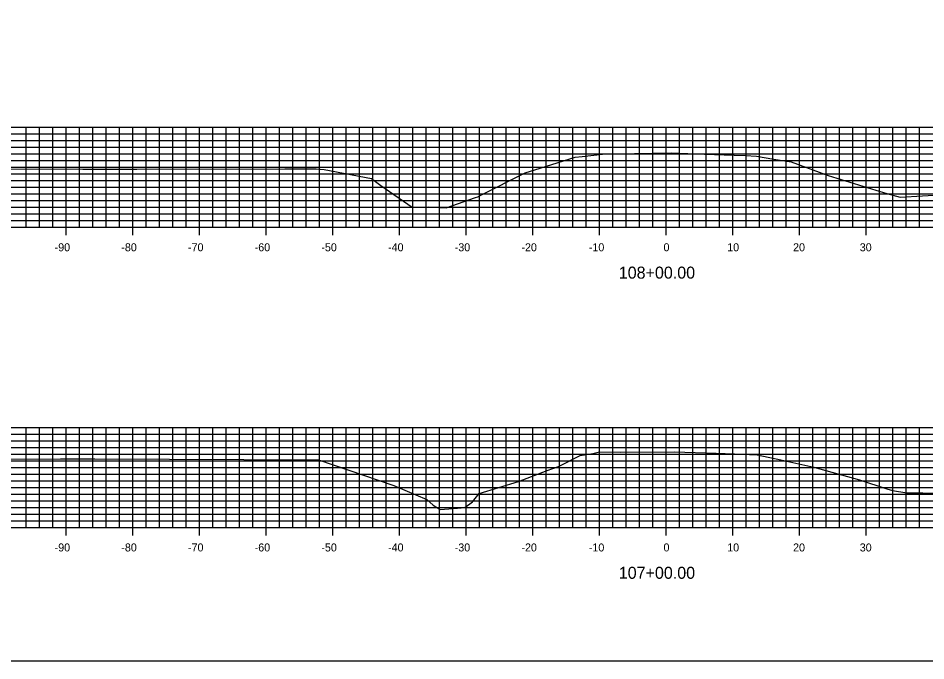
# Model space of a CAD drawing. Extents: x 1661012 to 1662122, y 670053 to 671852.
# Drawn here: x 1661094.8 to 1661230.9, y 671274.1 to 671370.5 of the extents above; entities that cross this region are included whole.
import ezdxf

# ---------------------------------------------------------------- set-up
doc = ezdxf.new("R2010")
doc.units = 0
for name, color, linetype in [('R_Concrete', 7, 'Continuous'), ('R_Concrete Hidden', 7, 'Continuous'), ('R_Erosion', 7, 'Continuous'), ('R_Exist Surface', 7, 'Continuous'), ('R_Proposed Road', 7, 'Continuous')]:
    doc.layers.add(name, color=color, linetype=linetype)

msp = doc.modelspace()

# ---------------------------------------------------------------- linework, layer by layer
at = {"layer": 'R_Concrete'}
for p, q in [((1661041.99, 671354.12), (1661341.99, 671354.12)), ((1661041.99, 671353.12), (1661341.99, 671353.12)), ((1661095.99, 671339.12), (1661095.99, 671354.12)), ((1661097.99, 671339.12), (1661097.99, 671354.12)), ((1661099.99, 671339.12), (1661099.99, 671354.12)), ((1661101.99, 671339.12), (1661101.99, 671354.12)), ((1661103.99, 671339.12), (1661103.99, 671354.12)), ((1661105.99, 671339.12), (1661105.99, 671354.12)), ((1661107.99, 671339.12), (1661107.99, 671354.12)), ((1661109.99, 671339.12), (1661109.99, 671354.12)), ((1661111.99, 671339.12), (1661111.99, 671354.12)), ((1661113.99, 671339.12), (1661113.99, 671354.12)), ((1661115.99, 671339.12), (1661115.99, 671354.12)), ((1661117.99, 671339.12), (1661117.99, 671354.12)), ((1661119.99, 671339.12), (1661119.99, 671354.12)), ((1661121.99, 671339.12), (1661121.99, 671354.12)), ((1661123.99, 671339.12), (1661123.99, 671354.12)), ((1661125.99, 671339.12), (1661125.99, 671354.12)), ((1661127.99, 671339.12), (1661127.99, 671354.12)), ((1661129.99, 671339.12), (1661129.99, 671354.12)), ((1661131.99, 671339.12), (1661131.99, 671354.12)), ((1661133.99, 671339.12), (1661133.99, 671354.12)), ((1661135.99, 671339.12), (1661135.99, 671354.12)), ((1661137.99, 671339.12), (1661137.99, 671354.12)), ((1661139.99, 671339.12), (1661139.99, 671354.12)), ((1661141.99, 671339.12), (1661141.99, 671354.12)), ((1661143.99, 671339.12), (1661143.99, 671354.12)), ((1661145.99, 671339.12), (1661145.99, 671354.12)), ((1661147.99, 671339.12), (1661147.99, 671354.12)), ((1661149.99, 671339.12), (1661149.99, 671354.12)), ((1661151.99, 671339.12), (1661151.99, 671354.12)), ((1661153.99, 671339.12), (1661153.99, 671354.12)), ((1661155.99, 671339.12), (1661155.99, 671354.12)), ((1661157.99, 671339.12), (1661157.99, 671354.12)), ((1661159.99, 671339.12), (1661159.99, 671354.12)), ((1661161.99, 671339.12), (1661161.99, 671354.12)), ((1661163.99, 671339.12), (1661163.99, 671354.12)), ((1661165.99, 671339.12), (1661165.99, 671354.12)), ((1661167.99, 671339.12), (1661167.99, 671354.12)), ((1661169.99, 671339.12), (1661169.99, 671354.12)), ((1661171.99, 671339.12), (1661171.99, 671354.12)), ((1661173.99, 671339.12), (1661173.99, 671354.12)), ((1661175.99, 671339.12), (1661175.99, 671354.12)), ((1661177.99, 671339.12), (1661177.99, 671354.12)), ((1661179.99, 671339.12), (1661179.99, 671354.12)), ((1661181.99, 671339.12), (1661181.99, 671354.12)), ((1661183.99, 671339.12), (1661183.99, 671354.12)), ((1661185.99, 671339.12), (1661185.99, 671354.12)), ((1661187.99, 671339.12), (1661187.99, 671354.12)), ((1661189.99, 671339.12), (1661189.99, 671354.12)), ((1661191.99, 671339.12), (1661191.99, 671354.12)), ((1661193.99, 671339.12), (1661193.99, 671354.12)), ((1661195.99, 671339.12), (1661195.99, 671354.12)), ((1661197.99, 671339.12), (1661197.99, 671354.12)), ((1661199.99, 671339.12), (1661199.99, 671354.12)), ((1661201.99, 671339.12), (1661201.99, 671354.12)), ((1661203.99, 671339.12), (1661203.99, 671354.12)), ((1661205.99, 671339.12), (1661205.99, 671354.12)), ((1661207.99, 671339.12), (1661207.99, 671354.12)), ((1661209.99, 671339.12), (1661209.99, 671354.12)), ((1661211.99, 671339.12), (1661211.99, 671354.12)), ((1661213.99, 671339.12), (1661213.99, 671354.12)), ((1661215.99, 671339.12), (1661215.99, 671354.12)), ((1661217.99, 671339.12), (1661217.99, 671354.12)), ((1661219.99, 671339.12), (1661219.99, 671354.12)), ((1661221.99, 671339.12), (1661221.99, 671354.12)), ((1661223.99, 671339.12), (1661223.99, 671354.12)), ((1661225.99, 671339.12), (1661225.99, 671354.12)), ((1661227.99, 671339.12), (1661227.99, 671354.12)), ((1661229.99, 671339.12), (1661229.99, 671354.12)), ((1661041.99, 671352.12), (1661341.99, 671352.12)), ((1661041.99, 671351.12), (1661341.99, 671351.12)), ((1661041.99, 671350.12), (1661341.99, 671350.12)), ((1661041.99, 671349.12), (1661341.99, 671349.12)), ((1661041.99, 671348.12), (1661341.99, 671348.12)), ((1661041.99, 671347.12), (1661341.99, 671347.12)), ((1661041.99, 671346.12), (1661341.99, 671346.12)), ((1661041.99, 671345.12), (1661341.99, 671345.12)), ((1661041.99, 671344.12), (1661341.99, 671344.12)), ((1661041.99, 671343.12), (1661341.99, 671343.12)), ((1661041.99, 671342.12), (1661341.99, 671342.12)), ((1661041.99, 671341.12), (1661341.99, 671341.12)), ((1661041.99, 671340.12), (1661341.99, 671340.12)), ((1661095.99, 671339.12), (1661095.99, 671339.72)), ((1661097.99, 671339.12), (1661097.99, 671339.72)), ((1661099.99, 671339.12), (1661099.99, 671339.72)), ((1661101.99, 671337.92), (1661101.99, 671340.32)), ((1661103.99, 671339.12), (1661103.99, 671339.72)), ((1661105.99, 671339.12), (1661105.99, 671339.72)), ((1661107.99, 671339.12), (1661107.99, 671339.72)), ((1661109.99, 671339.12), (1661109.99, 671339.72)), ((1661111.99, 671337.92), (1661111.99, 671340.32)), ((1661113.99, 671339.12), (1661113.99, 671339.72)), ((1661115.99, 671339.12), (1661115.99, 671339.72)), ((1661117.99, 671339.12), (1661117.99, 671339.72)), ((1661119.99, 671339.12), (1661119.99, 671339.72)), ((1661121.99, 671337.92), (1661121.99, 671340.32)), ((1661123.99, 671339.12), (1661123.99, 671339.72)), ((1661125.99, 671339.12), (1661125.99, 671339.72)), ((1661127.99, 671339.12), (1661127.99, 671339.72)), ((1661129.99, 671339.12), (1661129.99, 671339.72)), ((1661131.99, 671337.92), (1661131.99, 671340.32)), ((1661133.99, 671339.12), (1661133.99, 671339.72)), ((1661135.99, 671339.12), (1661135.99, 671339.72)), ((1661137.99, 671339.12), (1661137.99, 671339.72)), ((1661139.99, 671339.12), (1661139.99, 671339.72)), ((1661141.99, 671337.92), (1661141.99, 671340.32)), ((1661143.99, 671339.12), (1661143.99, 671339.72)), ((1661145.99, 671339.12), (1661145.99, 671339.72)), ((1661147.99, 671339.12), (1661147.99, 671339.72)), ((1661149.99, 671339.12), (1661149.99, 671339.72)), ((1661151.99, 671337.92), (1661151.99, 671340.32)), ((1661153.99, 671339.12), (1661153.99, 671339.72)), ((1661155.99, 671339.12), (1661155.99, 671339.72)), ((1661157.99, 671339.12), (1661157.99, 671339.72)), ((1661159.99, 671339.12), (1661159.99, 671339.72)), ((1661161.99, 671337.92), (1661161.99, 671340.32)), ((1661163.99, 671339.12), (1661163.99, 671339.72)), ((1661165.99, 671339.12), (1661165.99, 671339.72)), ((1661167.99, 671339.12), (1661167.99, 671339.72)), ((1661169.99, 671339.12), (1661169.99, 671339.72)), ((1661171.99, 671337.92), (1661171.99, 671340.32)), ((1661173.99, 671339.12), (1661173.99, 671339.72)), ((1661175.99, 671339.12), (1661175.99, 671339.72)), ((1661177.99, 671339.12), (1661177.99, 671339.72)), ((1661179.99, 671339.12), (1661179.99, 671339.72)), ((1661181.99, 671337.92), (1661181.99, 671340.32)), ((1661183.99, 671339.12), (1661183.99, 671339.72)), ((1661185.99, 671339.12), (1661185.99, 671339.72)), ((1661187.99, 671339.12), (1661187.99, 671339.72)), ((1661189.99, 671339.12), (1661189.99, 671339.72)), ((1661191.99, 671337.92), (1661191.99, 671340.32)), ((1661193.99, 671339.12), (1661193.99, 671339.72)), ((1661195.99, 671339.12), (1661195.99, 671339.72)), ((1661197.99, 671339.12), (1661197.99, 671339.72)), ((1661199.99, 671339.12), (1661199.99, 671339.72)), ((1661201.99, 671337.92), (1661201.99, 671340.32)), ((1661203.99, 671339.12), (1661203.99, 671339.72)), ((1661205.99, 671339.12), (1661205.99, 671339.72)), ((1661207.99, 671339.12), (1661207.99, 671339.72)), ((1661209.99, 671339.12), (1661209.99, 671339.72)), ((1661211.99, 671337.92), (1661211.99, 671340.32)), ((1661213.99, 671339.12), (1661213.99, 671339.72)), ((1661215.99, 671339.12), (1661215.99, 671339.72)), ((1661217.99, 671339.12), (1661217.99, 671339.72)), ((1661219.99, 671339.12), (1661219.99, 671339.72)), ((1661221.99, 671337.92), (1661221.99, 671340.32)), ((1661223.99, 671339.12), (1661223.99, 671339.72)), ((1661225.99, 671339.12), (1661225.99, 671339.72)), ((1661227.99, 671339.12), (1661227.99, 671339.72)), ((1661229.99, 671339.12), (1661229.99, 671339.72)), ((1661041.99, 671339.12), (1661341.99, 671339.12)), ((1661041.99, 671309.12), (1661341.99, 671309.12)), ((1661041.99, 671308.12), (1661341.99, 671308.12)), ((1661095.99, 671294.12), (1661095.99, 671309.12)), ((1661097.99, 671294.12), (1661097.99, 671309.12)), ((1661099.99, 671294.12), (1661099.99, 671309.12)), ((1661101.99, 671294.12), (1661101.99, 671309.12)), ((1661103.99, 671294.12), (1661103.99, 671309.12)), ((1661105.99, 671294.12), (1661105.99, 671309.12)), ((1661107.99, 671294.12), (1661107.99, 671309.12)), ((1661109.99, 671294.12), (1661109.99, 671309.12)), ((1661111.99, 671294.12), (1661111.99, 671309.12)), ((1661113.99, 671294.12), (1661113.99, 671309.12)), ((1661115.99, 671294.12), (1661115.99, 671309.12)), ((1661117.99, 671294.12), (1661117.99, 671309.12)), ((1661119.99, 671294.12), (1661119.99, 671309.12)), ((1661121.99, 671294.12), (1661121.99, 671309.12)), ((1661123.99, 671294.12), (1661123.99, 671309.12)), ((1661125.99, 671294.12), (1661125.99, 671309.12)), ((1661127.99, 671294.12), (1661127.99, 671309.12)), ((1661129.99, 671294.12), (1661129.99, 671309.12)), ((1661131.99, 671294.12), (1661131.99, 671309.12)), ((1661133.99, 671294.12), (1661133.99, 671309.12)), ((1661135.99, 671294.12), (1661135.99, 671309.12)), ((1661137.99, 671294.12), (1661137.99, 671309.12)), ((1661139.99, 671294.12), (1661139.99, 671309.12)), ((1661141.99, 671294.12), (1661141.99, 671309.12)), ((1661143.99, 671294.12), (1661143.99, 671309.12)), ((1661145.99, 671294.12), (1661145.99, 671309.12)), ((1661147.99, 671294.12), (1661147.99, 671309.12)), ((1661149.99, 671294.12), (1661149.99, 671309.12)), ((1661151.99, 671294.12), (1661151.99, 671309.12)), ((1661153.99, 671294.12), (1661153.99, 671309.12)), ((1661155.99, 671294.12), (1661155.99, 671309.12)), ((1661157.99, 671294.12), (1661157.99, 671309.12)), ((1661159.99, 671294.12), (1661159.99, 671309.12)), ((1661161.99, 671294.12), (1661161.99, 671309.12)), ((1661163.99, 671294.12), (1661163.99, 671309.12)), ((1661165.99, 671294.12), (1661165.99, 671309.12)), ((1661167.99, 671294.12), (1661167.99, 671309.12)), ((1661169.99, 671294.12), (1661169.99, 671309.12)), ((1661171.99, 671294.12), (1661171.99, 671309.12)), ((1661173.99, 671294.12), (1661173.99, 671309.12)), ((1661175.99, 671294.12), (1661175.99, 671309.12)), ((1661177.99, 671294.12), (1661177.99, 671309.12)), ((1661179.99, 671294.12), (1661179.99, 671309.12)), ((1661181.99, 671294.12), (1661181.99, 671309.12)), ((1661183.99, 671294.12), (1661183.99, 671309.12)), ((1661185.99, 671294.12), (1661185.99, 671309.12)), ((1661187.99, 671294.12), (1661187.99, 671309.12)), ((1661189.99, 671294.12), (1661189.99, 671309.12)), ((1661191.99, 671294.12), (1661191.99, 671309.12)), ((1661193.99, 671294.12), (1661193.99, 671309.12)), ((1661195.99, 671294.12), (1661195.99, 671309.12)), ((1661197.99, 671294.12), (1661197.99, 671309.12)), ((1661199.99, 671294.12), (1661199.99, 671309.12)), ((1661201.99, 671294.12), (1661201.99, 671309.12)), ((1661203.99, 671294.12), (1661203.99, 671309.12)), ((1661205.99, 671294.12), (1661205.99, 671309.12)), ((1661207.99, 671294.12), (1661207.99, 671309.12)), ((1661209.99, 671294.12), (1661209.99, 671309.12)), ((1661211.99, 671294.12), (1661211.99, 671309.12)), ((1661213.99, 671294.12), (1661213.99, 671309.12)), ((1661215.99, 671294.12), (1661215.99, 671309.12)), ((1661217.99, 671294.12), (1661217.99, 671309.12)), ((1661219.99, 671294.12), (1661219.99, 671309.12)), ((1661221.99, 671294.12), (1661221.99, 671309.12)), ((1661223.99, 671294.12), (1661223.99, 671309.12)), ((1661225.99, 671294.12), (1661225.99, 671309.12)), ((1661227.99, 671294.12), (1661227.99, 671309.12)), ((1661229.99, 671294.12), (1661229.99, 671309.12)), ((1661041.99, 671307.12), (1661341.99, 671307.12)), ((1661041.99, 671306.12), (1661341.99, 671306.12)), ((1661041.99, 671305.12), (1661341.99, 671305.12)), ((1661041.99, 671304.12), (1661341.99, 671304.12)), ((1661041.99, 671303.12), (1661341.99, 671303.12)), ((1661041.99, 671302.12), (1661341.99, 671302.12)), ((1661041.99, 671301.12), (1661341.99, 671301.12)), ((1661041.99, 671300.12), (1661341.99, 671300.12)), ((1661041.99, 671299.12), (1661341.99, 671299.12)), ((1661041.99, 671298.12), (1661341.99, 671298.12)), ((1661041.99, 671297.12), (1661341.99, 671297.12)), ((1661041.99, 671296.12), (1661341.99, 671296.12)), ((1661041.99, 671295.12), (1661341.99, 671295.12)), ((1661095.99, 671294.12), (1661095.99, 671294.72)), ((1661097.99, 671294.12), (1661097.99, 671294.72)), ((1661099.99, 671294.12), (1661099.99, 671294.72)), ((1661101.99, 671292.92), (1661101.99, 671295.32)), ((1661103.99, 671294.12), (1661103.99, 671294.72)), ((1661105.99, 671294.12), (1661105.99, 671294.72)), ((1661107.99, 671294.12), (1661107.99, 671294.72)), ((1661109.99, 671294.12), (1661109.99, 671294.72)), ((1661111.99, 671292.92), (1661111.99, 671295.32)), ((1661113.99, 671294.12), (1661113.99, 671294.72)), ((1661115.99, 671294.12), (1661115.99, 671294.72)), ((1661117.99, 671294.12), (1661117.99, 671294.72)), ((1661119.99, 671294.12), (1661119.99, 671294.72)), ((1661121.99, 671292.92), (1661121.99, 671295.32)), ((1661123.99, 671294.12), (1661123.99, 671294.72)), ((1661125.99, 671294.12), (1661125.99, 671294.72)), ((1661127.99, 671294.12), (1661127.99, 671294.72)), ((1661129.99, 671294.12), (1661129.99, 671294.72)), ((1661131.99, 671292.92), (1661131.99, 671295.32)), ((1661133.99, 671294.12), (1661133.99, 671294.72)), ((1661135.99, 671294.12), (1661135.99, 671294.72)), ((1661137.99, 671294.12), (1661137.99, 671294.72)), ((1661139.99, 671294.12), (1661139.99, 671294.72)), ((1661141.99, 671292.92), (1661141.99, 671295.32)), ((1661143.99, 671294.12), (1661143.99, 671294.72)), ((1661145.99, 671294.12), (1661145.99, 671294.72)), ((1661147.99, 671294.12), (1661147.99, 671294.72)), ((1661149.99, 671294.12), (1661149.99, 671294.72)), ((1661151.99, 671292.92), (1661151.99, 671295.32)), ((1661153.99, 671294.12), (1661153.99, 671294.72)), ((1661155.99, 671294.12), (1661155.99, 671294.72)), ((1661157.99, 671294.12), (1661157.99, 671294.72)), ((1661159.99, 671294.12), (1661159.99, 671294.72)), ((1661161.99, 671292.92), (1661161.99, 671295.32)), ((1661163.99, 671294.12), (1661163.99, 671294.72)), ((1661165.99, 671294.12), (1661165.99, 671294.72)), ((1661167.99, 671294.12), (1661167.99, 671294.72)), ((1661169.99, 671294.12), (1661169.99, 671294.72)), ((1661171.99, 671292.92), (1661171.99, 671295.32)), ((1661173.99, 671294.12), (1661173.99, 671294.72)), ((1661175.99, 671294.12), (1661175.99, 671294.72)), ((1661177.99, 671294.12), (1661177.99, 671294.72)), ((1661179.99, 671294.12), (1661179.99, 671294.72)), ((1661181.99, 671292.92), (1661181.99, 671295.32)), ((1661183.99, 671294.12), (1661183.99, 671294.72)), ((1661185.99, 671294.12), (1661185.99, 671294.72)), ((1661187.99, 671294.12), (1661187.99, 671294.72)), ((1661189.99, 671294.12), (1661189.99, 671294.72)), ((1661191.99, 671292.92), (1661191.99, 671295.32)), ((1661193.99, 671294.12), (1661193.99, 671294.72)), ((1661195.99, 671294.12), (1661195.99, 671294.72)), ((1661197.99, 671294.12), (1661197.99, 671294.72)), ((1661199.99, 671294.12), (1661199.99, 671294.72)), ((1661201.99, 671292.92), (1661201.99, 671295.32)), ((1661203.99, 671294.12), (1661203.99, 671294.72)), ((1661205.99, 671294.12), (1661205.99, 671294.72)), ((1661207.99, 671294.12), (1661207.99, 671294.72)), ((1661209.99, 671294.12), (1661209.99, 671294.72)), ((1661211.99, 671292.92), (1661211.99, 671295.32)), ((1661213.99, 671294.12), (1661213.99, 671294.72)), ((1661215.99, 671294.12), (1661215.99, 671294.72)), ((1661217.99, 671294.12), (1661217.99, 671294.72)), ((1661219.99, 671294.12), (1661219.99, 671294.72)), ((1661221.99, 671292.92), (1661221.99, 671295.32)), ((1661223.99, 671294.12), (1661223.99, 671294.72)), ((1661225.99, 671294.12), (1661225.99, 671294.72)), ((1661227.99, 671294.12), (1661227.99, 671294.72)), ((1661229.99, 671294.12), (1661229.99, 671294.72)), ((1661041.99, 671294.12), (1661341.99, 671294.12))]:
    msp.add_line(p, q, dxfattribs=at)
at = {"layer": 'R_Erosion'}
for points in [[(1661075.06, 671347.9), (1661104.52, 671347.85), (1661112.58, 671347.84), (1661134.82, 671347.89), (1661139.52, 671347.9), (1661140.68, 671347.76), (1661147.82, 671346.42), (1661149.18, 671345.4), (1661153.88, 671342.15), (1661156.36, 671342.18), (1661159, 671342.01), (1661163.38, 671343.57), (1661163.75, 671343.69), (1661164.18, 671343.91), (1661170.84, 671347.26), (1661173.1, 671347.96), (1661178.32, 671349.61), (1661179.37, 671349.71), (1661182.44, 671350.1), (1661187.22, 671350.2), (1661192.78, 671350.27), (1661197.73, 671350.07), (1661202.17, 671349.95), (1661203.88, 671349.86), (1661205.51, 671349.76), (1661208.11, 671349.32), (1661210.72, 671348.93), (1661216.29, 671346.88), (1661223.42, 671344.69), (1661225.07, 671344.17), (1661227.08, 671343.62), (1661233.77, 671344.03)], [(1661073.14, 671304.23), (1661101.18, 671304.4), (1661104.35, 671304.42), (1661105.03, 671304.42), (1661106.32, 671304.42), (1661139.87, 671304.27), (1661151.13, 671300.39), (1661156.08, 671298.29), (1661157.04, 671297.45), (1661158.09, 671296.81), (1661160.71, 671297.01), (1661161.79, 671297.09), (1661162.95, 671297.95), (1661163.93, 671299.21), (1661169.85, 671301), (1661174.14, 671302.67), (1661175.85, 671303.25), (1661179.07, 671304.89), (1661181.01, 671305.22), (1661181.97, 671305.43), (1661185.15, 671305.42), (1661193.22, 671305.43), (1661199.5, 671305.25), (1661202.25, 671305.15), (1661203.29, 671305.12), (1661205.64, 671304.99), (1661209.18, 671304.23), (1661214.11, 671303.17), (1661220.97, 671301.24), (1661225.07, 671299.89), (1661225.93, 671299.67), (1661228.07, 671299.31), (1661230.5, 671299.31), (1661233.53, 671299.27)]]:
    msp.add_lwpolyline(points, dxfattribs=at)
at = {"layer": 'R_Exist Surface'}
for p, q in [((1661041.99, 671339.12), (1661341.99, 671339.12)), ((1661041.99, 671294.12), (1661341.99, 671294.12))]:
    msp.add_line(p, q, dxfattribs=at)
at = {"layer": 'R_Proposed Road'}
msp.add_lwpolyline([(1661011.99, 671274.12), (1661371.99, 671274.12), (1661371.99, 671466.82), (1661011.99, 671466.82)], close=True, dxfattribs=at)

# ---------------------------------------------------------------- texts
at = {"layer": 'R_Concrete Hidden'}
for s, height, p in [('-90', 1.2, (1661100.28, 671335.52)), ('-80', 1.2, (1661110.28, 671335.52)), ('-70', 1.2, (1661120.28, 671335.52)), ('-60', 1.2, (1661130.28, 671335.52)), ('-50', 1.2, (1661140.28, 671335.52)), ('-40', 1.2, (1661150.28, 671335.52)), ('-30', 1.2, (1661160.28, 671335.52)), ('-20', 1.2, (1661170.28, 671335.52)), ('-10', 1.2, (1661180.39, 671335.52)), ('0', 1.2, (1661191.59, 671335.52)), ('10', 1.2, (1661201.14, 671335.52)), ('20', 1.2, (1661211.02, 671335.52)), ('30', 1.2, (1661221.02, 671335.52)), ('108+00.00', 1.8, (1661184.88, 671331.42)), ('-90', 1.2, (1661100.28, 671290.52)), ('-80', 1.2, (1661110.28, 671290.52)), ('-70', 1.2, (1661120.28, 671290.52)), ('-60', 1.2, (1661130.28, 671290.52)), ('-50', 1.2, (1661140.28, 671290.52)), ('-40', 1.2, (1661150.28, 671290.52)), ('-30', 1.2, (1661160.28, 671290.52)), ('-20', 1.2, (1661170.28, 671290.52)), ('-10', 1.2, (1661180.39, 671290.52)), ('0', 1.2, (1661191.59, 671290.52)), ('10', 1.2, (1661201.14, 671290.52)), ('20', 1.2, (1661211.02, 671290.52)), ('30', 1.2, (1661221.02, 671290.52)), ('107+00.00', 1.8, (1661184.88, 671286.42))]:
    msp.add_text(s, height=height, dxfattribs=at).set_placement(p)

doc.saveas('drawing.dxf')
